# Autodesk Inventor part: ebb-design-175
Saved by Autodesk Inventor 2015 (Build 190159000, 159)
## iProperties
Created: 2020-07
Part Number: ebb-design-175
Checked By: TraceParts S.A.
Material: Generic
Catalog Web Link: www.traceparts.com
Document SubType Name: Modeling
Designer: TraceParts
Density: 1 g/cm^3
Appearance: Default
Company: TraceParts S.A.
Author: TraceParts
REFERENCE: EBB-DESIGN-175
DESIGN: EBB-DESIGN-175
SUPPLIER: Soler & Palau
TraceParts.PartNumber: 10-04022019-080829
TraceParts.PartTitle: EBB-DESIGN
TraceParts.InstanceId: 10-04022019-08082962DTJOZIL7JA3E4R4GZHJW4RH
TraceParts.PartStatus: Published
TraceParts.PartVersion: 1.0.1
TRACEPARTS: TRACEPARTS
TraceParts.PartLanguage: en
TraceParts.ClassPath: SOLER_PALAU:10-04022019-080829
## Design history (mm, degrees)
feature "ebb-design-175"
body "Solid1"
